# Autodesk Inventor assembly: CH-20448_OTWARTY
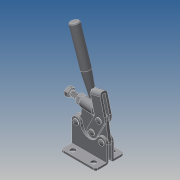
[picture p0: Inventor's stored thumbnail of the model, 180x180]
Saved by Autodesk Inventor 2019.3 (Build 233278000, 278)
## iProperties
Company: ·L?¤¤?
Created: 2010-06
Part Number: CH-20448_OTWARTY
Material: Ogólny
Description: STEP AP203
Document SubType Name: Assembly
Designer: CADENGINEERING4
Sending System: SolidWorks 2005179
Preprocessor: SwSTEP 2.0
Title: CH-20448.STEP
Author: ·L?¥Î?
Revision Number: ANY
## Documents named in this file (8)
- E:\STRONA\Horizontal toggle clamp\CH-20448\CH-20448_OTWARTY.iam
- E:\STRONA\Horizontal toggle clamp\CH-20448\20448-05___.ipt
- E:\STRONA\Horizontal toggle clamp\CH-20448\20448-02____ûV¡ø_.ipt
- E:\STRONA\Horizontal toggle clamp\CH-20448\M10___.ipt
- E:\STRONA\Horizontal toggle clamp\CH-20448\20448-03___.ipt
- E:\STRONA\Horizontal toggle clamp\CH-20448\CH-FC-105015___.ipt
- E:\STRONA\Horizontal toggle clamp\CH-20448\20448-01___.ipt
- E:\STRONA\Horizontal toggle clamp\CH-20448\20448-04____ûV¡ø_.ipt
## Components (10 placed, 10 different names)
1. 20448-05_??_1 — Zestawiające:6, Zestawiające:7
2. 20448-02_??<ûV¡ø>_2 — Równoległe:1, Zestawiające:2, Zestawiające:3, Zestawiające:12, Zestawiające:13, Zestawiające:16
3. M10_??_3 — Zestawiające:1, Zestawiające:2
4. 20448-03_??_4 — Zestawiające:4, Zestawiające:5, Zestawiające:8, Zestawiające:9
5. 20448-05_??_5 — Zestawiające:17, Zestawiające:18
6. CH-FC-105015_??_6 — Równoległe:1, Zestawiające:1, Zestawiające:3
7. 20448-01_??_7 — Zestawiające:4, Zestawiające:5, Zestawiające:6, Zestawiające:7, Zestawiające:12, Zestawiające:13, Zestawiające:14, Zestawiające:15, Kątowe:1
8. 20448-05_??_8 — Zestawiające:10, Zestawiające:11
9. 20448-04_??<ûV¡ø>_9 — Zestawiające:8, Zestawiające:9, Zestawiające:10, Zestawiające:11, Zestawiające:16, Zestawiające:17, Zestawiające:18, Kątowe:1
10. 20448-05_??_10 — Zestawiające:14, Zestawiające:15
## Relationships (20: Mate 18, Flush 1, Angle 1)
- Równoległe:1 [Flush]: 20448-02_??<ûV¡ø>_2 ↔ CH-FC-105015_??_6
- Zestawiające:1 [Mate]: M10_??_3 ↔ CH-FC-105015_??_6
- Zestawiające:2 [Mate]: 20448-02_??<ûV¡ø>_2 ↔ M10_??_3
- Zestawiające:3 [Mate]: 20448-02_??<ûV¡ø>_2 ↔ CH-FC-105015_??_6
- Zestawiające:4 [Mate]: 20448-03_??_4 ↔ 20448-01_??_7
- Zestawiające:5 [Mate]: 20448-03_??_4 ↔ 20448-01_??_7
- Zestawiające:6 [Mate]: 20448-05_??_1 ↔ 20448-01_??_7
- Zestawiające:7 [Mate]: 20448-05_??_1 ↔ 20448-01_??_7
- Zestawiające:8 [Mate]: 20448-03_??_4 ↔ 20448-04_??<ûV¡ø>_9
- Zestawiające:9 [Mate]: 20448-03_??_4 ↔ 20448-04_??<ûV¡ø>_9
- Zestawiające:10 [Mate]: 20448-05_??_8 ↔ 20448-04_??<ûV¡ø>_9
- Zestawiające:11 [Mate]: 20448-05_??_8 ↔ 20448-04_??<ûV¡ø>_9
- Zestawiające:12 [Mate]: 20448-02_??<ûV¡ø>_2 ↔ 20448-01_??_7
- Zestawiające:13 [Mate]: 20448-02_??<ûV¡ø>_2 ↔ 20448-01_??_7
- Zestawiające:14 [Mate]: 20448-01_??_7 ↔ 20448-05_??_10
- Zestawiające:15 [Mate]: 20448-01_??_7 ↔ 20448-05_??_10
- Zestawiające:16 [Mate]: 20448-02_??<ûV¡ø>_2 ↔ 20448-04_??<ûV¡ø>_9
- Zestawiające:17 [Mate]: 20448-05_??_5 ↔ 20448-04_??<ûV¡ø>_9
- Zestawiające:18 [Mate]: 20448-05_??_5 ↔ 20448-04_??<ûV¡ø>_9
- Kątowe:1 [Angle]: 20448-01_??_7 ↔ 20448-04_??<ûV¡ø>_9
